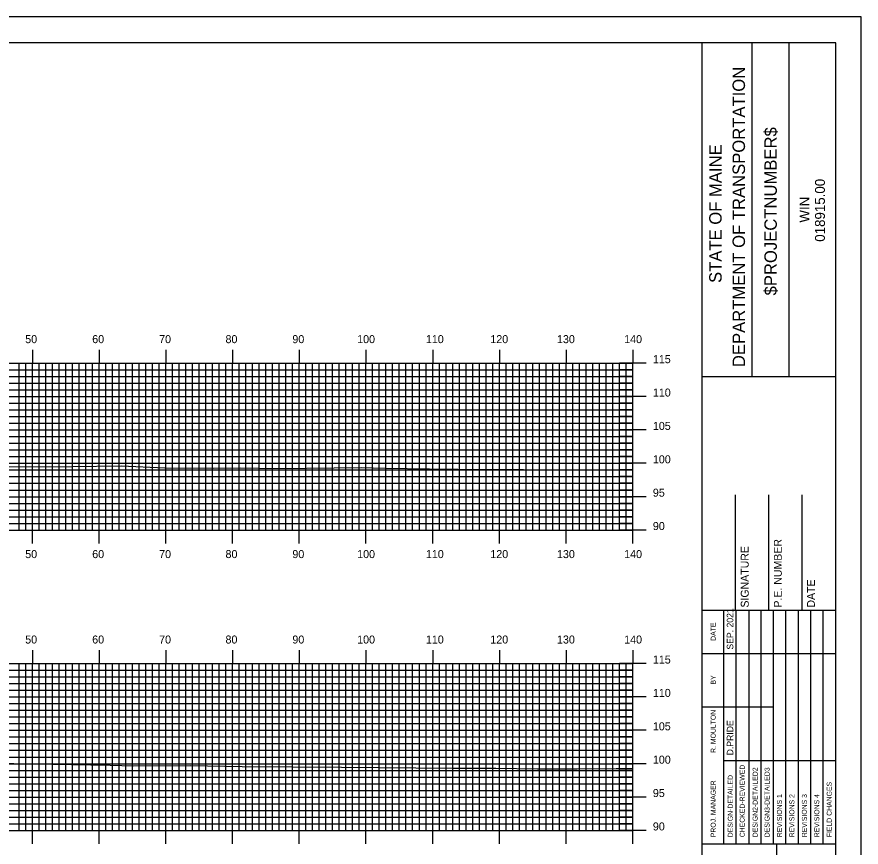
# Model space of a CAD drawing. Extents: x 1773990 to 1774333, y 442591 to 442811.
# Drawn here: x 1774203.3 to 1774329.9, y 442686.2 to 442810.5 of the extents above; entities that cross this region are included whole.
import ezdxf

# ---------------------------------------------------------------- set-up
doc = ezdxf.new("R2010")
doc.units = 0
for name, color, linetype in [('BORDER', 7, 'Continuous'), ('H_V ANNOTATION', 7, 'Continuous'), ('MAJOR', 7, 'Continuous'), ('MINOR', 7, 'Continuous'), ('PLOT BOUNDARY', 7, 'Continuous'), ('S_Roadway_Centerline', 7, 'Continuous')]:
    doc.layers.add(name, color=color, linetype=linetype)

msp = doc.modelspace()

# ---------------------------------------------------------------- linework, layer by layer
at = {"layer": 'BORDER'}
for p, q in [((1774306.06, 442596.67), (1774306.06, 442806.67)), ((1774313.52, 442756.66), (1774313.52, 442806.66)), ((1774319.11, 442756.66), (1774319.11, 442806.66)), ((1774306.06, 442756.65), (1774326.06, 442756.65)), ((1774311.06, 442721.67), (1774311.06, 442738.97)), ((1774316.06, 442721.67), (1774316.06, 442738.97)), ((1774321.06, 442721.67), (1774321.06, 442738.97)), ((1774306.06, 442721.67), (1774326.06, 442721.67)), ((1774306.06, 442686.67), (1774326.06, 442686.67)), ((1774317.24, 442616.67), (1774317.24, 442686.67))]:
    msp.add_line(p, q, dxfattribs=at)
msp.add_lwpolyline([(1774006.06, 442596.67), (1774326.06, 442596.67), (1774326.06, 442806.67), (1774006.06, 442806.67)], close=True, dxfattribs=at)
for points in [[(1774309.29, 442715.17), (1774309.29, 442721.67)], [(1774311.15, 442686.68), (1774311.15, 442721.67)], [(1774313.02, 442721.67), (1774313.02, 442686.68)], [(1774314.88, 442686.68), (1774314.88, 442721.67)], [(1774316.74, 442686.68), (1774316.74, 442721.67)], [(1774318.61, 442686.68), (1774318.61, 442721.67)], [(1774320.47, 442686.68), (1774320.47, 442721.67)], [(1774322.33, 442686.68), (1774322.33, 442721.67)], [(1774324.2, 442686.68), (1774324.2, 442721.67)], [(1774309.29, 442686.68), (1774309.29, 442720.26)], [(1774306.06, 442715.17), (1774326.06, 442715.17)], [(1774306.06, 442707.17), (1774309.29, 442707.17)], [(1774309.29, 442707.17), (1774316.74, 442707.17)], [(1774309.29, 442699.17), (1774326.06, 442699.17)]]:
    msp.add_lwpolyline(points, dxfattribs=at)
at = {"layer": 'MAJOR'}
for p, q in [((1774205.66, 442760.67), (1774205.66, 442758.67)), ((1774215.66, 442760.67), (1774215.66, 442758.67)), ((1774225.66, 442760.67), (1774225.66, 442758.67)), ((1774235.66, 442760.67), (1774235.66, 442758.67)), ((1774245.66, 442760.67), (1774245.66, 442758.67)), ((1774255.66, 442760.67), (1774255.66, 442758.67)), ((1774265.66, 442760.67), (1774265.66, 442758.67)), ((1774275.66, 442760.67), (1774275.66, 442758.67)), ((1774285.66, 442760.67), (1774285.66, 442758.67)), ((1774295.66, 442760.67), (1774295.66, 442758.67)), ((1774015.66, 442758.67), (1774295.66, 442758.67)), ((1774015.66, 442758.67), (1774295.66, 442758.67)), ((1774205.66, 442733.67), (1774205.66, 442758.67)), ((1774215.66, 442733.67), (1774215.66, 442758.67)), ((1774225.66, 442733.67), (1774225.66, 442758.67)), ((1774235.66, 442733.67), (1774235.66, 442758.67)), ((1774245.66, 442733.67), (1774245.66, 442758.67)), ((1774255.66, 442733.67), (1774255.66, 442758.67)), ((1774265.66, 442733.67), (1774265.66, 442758.67)), ((1774275.66, 442733.67), (1774275.66, 442758.67)), ((1774285.66, 442733.67), (1774285.66, 442758.67)), ((1774297.66, 442758.67), (1774293.65, 442758.67)), ((1774295.66, 442733.67), (1774295.66, 442758.67)), ((1774295.66, 442733.67), (1774295.66, 442758.67)), ((1774015.66, 442753.67), (1774295.66, 442753.67)), ((1774297.66, 442753.67), (1774293.65, 442753.67)), ((1774015.66, 442748.67), (1774295.66, 442748.67)), ((1774297.66, 442748.67), (1774293.65, 442748.67)), ((1774015.66, 442743.67), (1774295.66, 442743.67)), ((1774297.66, 442743.67), (1774293.65, 442743.67)), ((1774015.66, 442738.67), (1774295.66, 442738.67)), ((1774297.66, 442738.67), (1774293.65, 442738.67)), ((1774015.66, 442733.67), (1774295.66, 442733.67)), ((1774015.66, 442733.67), (1774295.66, 442733.67)), ((1774205.66, 442731.66), (1774205.66, 442733.67)), ((1774215.66, 442731.66), (1774215.66, 442733.67)), ((1774225.66, 442731.66), (1774225.66, 442733.67)), ((1774235.66, 442731.66), (1774235.66, 442733.67)), ((1774245.66, 442731.66), (1774245.66, 442733.67)), ((1774255.66, 442731.66), (1774255.66, 442733.67)), ((1774265.66, 442731.66), (1774265.66, 442733.67)), ((1774275.66, 442731.66), (1774275.66, 442733.67)), ((1774285.66, 442731.66), (1774285.66, 442733.67)), ((1774297.66, 442733.67), (1774293.65, 442733.67)), ((1774295.66, 442731.66), (1774295.66, 442733.67)), ((1774205.66, 442715.67), (1774205.66, 442713.67)), ((1774215.66, 442715.67), (1774215.66, 442713.67)), ((1774225.66, 442715.67), (1774225.66, 442713.67)), ((1774235.66, 442715.67), (1774235.66, 442713.67)), ((1774245.66, 442715.67), (1774245.66, 442713.67)), ((1774255.66, 442715.67), (1774255.66, 442713.67)), ((1774265.66, 442715.67), (1774265.66, 442713.67)), ((1774275.66, 442715.67), (1774275.66, 442713.67)), ((1774285.66, 442715.67), (1774285.66, 442713.67)), ((1774295.66, 442715.67), (1774295.66, 442713.67)), ((1774015.66, 442713.67), (1774295.66, 442713.67)), ((1774015.66, 442713.67), (1774295.66, 442713.67)), ((1774205.66, 442688.67), (1774205.66, 442713.67)), ((1774215.66, 442688.67), (1774215.66, 442713.67)), ((1774225.66, 442688.67), (1774225.66, 442713.67)), ((1774235.66, 442688.67), (1774235.66, 442713.67)), ((1774245.66, 442688.67), (1774245.66, 442713.67)), ((1774255.66, 442688.67), (1774255.66, 442713.67)), ((1774265.66, 442688.67), (1774265.66, 442713.67)), ((1774275.66, 442688.67), (1774275.66, 442713.67)), ((1774285.66, 442688.67), (1774285.66, 442713.67)), ((1774297.66, 442713.67), (1774293.65, 442713.67)), ((1774295.66, 442688.67), (1774295.66, 442713.67)), ((1774295.66, 442688.67), (1774295.66, 442713.67)), ((1774015.66, 442708.67), (1774295.66, 442708.67)), ((1774297.66, 442708.67), (1774293.65, 442708.67)), ((1774015.66, 442703.67), (1774295.66, 442703.67)), ((1774297.66, 442703.67), (1774293.65, 442703.67)), ((1774015.66, 442698.67), (1774295.66, 442698.67)), ((1774297.66, 442698.67), (1774293.65, 442698.67)), ((1774015.66, 442693.67), (1774295.66, 442693.67)), ((1774297.66, 442693.67), (1774293.65, 442693.67)), ((1774015.66, 442688.67), (1774295.66, 442688.67)), ((1774015.66, 442688.67), (1774295.66, 442688.67)), ((1774205.66, 442686.66), (1774205.66, 442688.67)), ((1774215.66, 442686.66), (1774215.66, 442688.67)), ((1774225.66, 442686.66), (1774225.66, 442688.67)), ((1774235.66, 442686.66), (1774235.66, 442688.67)), ((1774245.66, 442686.66), (1774245.66, 442688.67)), ((1774255.66, 442686.66), (1774255.66, 442688.67)), ((1774265.66, 442686.66), (1774265.66, 442688.67)), ((1774275.66, 442686.66), (1774275.66, 442688.67)), ((1774285.66, 442686.66), (1774285.66, 442688.67)), ((1774297.66, 442688.67), (1774293.65, 442688.67)), ((1774295.66, 442686.66), (1774295.66, 442688.67))]:
    msp.add_line(p, q, dxfattribs=at)
at = {"layer": 'MINOR'}
for p, q in [((1774203.66, 442733.67), (1774203.66, 442758.67)), ((1774204.66, 442733.67), (1774204.66, 442758.67)), ((1774206.66, 442733.67), (1774206.66, 442758.67)), ((1774207.66, 442733.67), (1774207.66, 442758.67)), ((1774208.66, 442733.67), (1774208.66, 442758.67)), ((1774209.66, 442733.67), (1774209.66, 442758.67)), ((1774210.66, 442733.67), (1774210.66, 442758.67)), ((1774211.66, 442733.67), (1774211.66, 442758.67)), ((1774212.66, 442733.67), (1774212.66, 442758.67)), ((1774213.66, 442733.67), (1774213.66, 442758.67)), ((1774214.66, 442733.67), (1774214.66, 442758.67)), ((1774216.66, 442733.67), (1774216.66, 442758.67)), ((1774217.66, 442733.67), (1774217.66, 442758.67)), ((1774218.66, 442733.67), (1774218.66, 442758.67)), ((1774219.66, 442733.67), (1774219.66, 442758.67)), ((1774220.66, 442733.67), (1774220.66, 442758.67)), ((1774221.66, 442733.67), (1774221.66, 442758.67)), ((1774222.66, 442733.67), (1774222.66, 442758.67)), ((1774223.66, 442733.67), (1774223.66, 442758.67)), ((1774224.66, 442733.67), (1774224.66, 442758.67)), ((1774226.66, 442733.67), (1774226.66, 442758.67)), ((1774227.66, 442733.67), (1774227.66, 442758.67)), ((1774228.66, 442733.67), (1774228.66, 442758.67)), ((1774229.66, 442733.67), (1774229.66, 442758.67)), ((1774230.66, 442733.67), (1774230.66, 442758.67)), ((1774231.66, 442733.67), (1774231.66, 442758.67)), ((1774232.66, 442733.67), (1774232.66, 442758.67)), ((1774233.66, 442733.67), (1774233.66, 442758.67)), ((1774234.66, 442733.67), (1774234.66, 442758.67)), ((1774236.66, 442733.67), (1774236.66, 442758.67)), ((1774237.66, 442733.67), (1774237.66, 442758.67)), ((1774238.66, 442733.67), (1774238.66, 442758.67)), ((1774239.66, 442733.67), (1774239.66, 442758.67)), ((1774240.66, 442733.67), (1774240.66, 442758.67)), ((1774241.66, 442733.67), (1774241.66, 442758.67)), ((1774242.66, 442733.67), (1774242.66, 442758.67)), ((1774243.66, 442733.67), (1774243.66, 442758.67)), ((1774244.66, 442733.67), (1774244.66, 442758.67)), ((1774246.66, 442733.67), (1774246.66, 442758.67)), ((1774247.66, 442733.67), (1774247.66, 442758.67)), ((1774248.66, 442733.67), (1774248.66, 442758.67)), ((1774249.66, 442733.67), (1774249.66, 442758.67)), ((1774250.66, 442733.67), (1774250.66, 442758.67)), ((1774251.66, 442733.67), (1774251.66, 442758.67)), ((1774252.66, 442733.67), (1774252.66, 442758.67)), ((1774253.66, 442733.67), (1774253.66, 442758.67)), ((1774254.66, 442733.67), (1774254.66, 442758.67)), ((1774256.66, 442733.67), (1774256.66, 442758.67)), ((1774257.66, 442733.67), (1774257.66, 442758.67)), ((1774258.66, 442733.67), (1774258.66, 442758.67)), ((1774259.66, 442733.67), (1774259.66, 442758.67)), ((1774260.66, 442733.67), (1774260.66, 442758.67)), ((1774261.66, 442733.67), (1774261.66, 442758.67)), ((1774262.66, 442733.67), (1774262.66, 442758.67)), ((1774263.66, 442733.67), (1774263.66, 442758.67)), ((1774264.66, 442733.67), (1774264.66, 442758.67)), ((1774266.66, 442733.67), (1774266.66, 442758.67)), ((1774267.66, 442733.67), (1774267.66, 442758.67)), ((1774268.66, 442733.67), (1774268.66, 442758.67)), ((1774269.66, 442733.67), (1774269.66, 442758.67)), ((1774270.66, 442733.67), (1774270.66, 442758.67)), ((1774271.66, 442733.67), (1774271.66, 442758.67)), ((1774272.66, 442733.67), (1774272.66, 442758.67)), ((1774273.66, 442733.67), (1774273.66, 442758.67)), ((1774274.66, 442733.67), (1774274.66, 442758.67)), ((1774276.66, 442733.67), (1774276.66, 442758.67)), ((1774277.66, 442733.67), (1774277.66, 442758.67)), ((1774278.66, 442733.67), (1774278.66, 442758.67)), ((1774279.66, 442733.67), (1774279.66, 442758.67)), ((1774280.66, 442733.67), (1774280.66, 442758.67)), ((1774281.66, 442733.67), (1774281.66, 442758.67)), ((1774282.66, 442733.67), (1774282.66, 442758.67)), ((1774283.66, 442733.67), (1774283.66, 442758.67)), ((1774284.66, 442733.67), (1774284.66, 442758.67)), ((1774286.66, 442733.67), (1774286.66, 442758.67)), ((1774287.66, 442733.67), (1774287.66, 442758.67)), ((1774288.66, 442733.67), (1774288.66, 442758.67)), ((1774289.66, 442733.67), (1774289.66, 442758.67)), ((1774290.66, 442733.67), (1774290.66, 442758.67)), ((1774291.66, 442733.67), (1774291.66, 442758.67)), ((1774292.66, 442733.67), (1774292.66, 442758.67)), ((1774293.66, 442733.67), (1774293.66, 442758.67)), ((1774294.66, 442733.67), (1774294.66, 442758.67)), ((1774015.66, 442757.67), (1774295.66, 442757.67)), ((1774295.66, 442757.67), (1774293.65, 442757.67)), ((1774015.66, 442756.67), (1774295.66, 442756.67)), ((1774295.66, 442756.67), (1774293.65, 442756.67)), ((1774015.66, 442755.67), (1774295.66, 442755.67)), ((1774015.66, 442754.67), (1774295.66, 442754.67)), ((1774295.66, 442755.67), (1774293.65, 442755.67)), ((1774295.66, 442754.67), (1774293.65, 442754.67)), ((1774015.66, 442752.67), (1774295.66, 442752.67)), ((1774295.66, 442752.67), (1774293.65, 442752.67)), ((1774015.66, 442751.67), (1774295.66, 442751.67)), ((1774295.66, 442751.67), (1774293.65, 442751.67)), ((1774015.66, 442750.67), (1774295.66, 442750.67)), ((1774015.66, 442749.67), (1774295.66, 442749.67)), ((1774295.66, 442750.67), (1774293.65, 442750.67)), ((1774295.66, 442749.67), (1774293.65, 442749.67)), ((1774015.66, 442747.67), (1774295.66, 442747.67)), ((1774295.66, 442747.67), (1774293.65, 442747.67)), ((1774015.66, 442746.67), (1774295.66, 442746.67)), ((1774295.66, 442746.67), (1774293.65, 442746.67)), ((1774015.66, 442745.67), (1774295.66, 442745.67)), ((1774015.66, 442744.67), (1774295.66, 442744.67)), ((1774295.66, 442745.67), (1774293.65, 442745.67)), ((1774295.66, 442744.67), (1774293.65, 442744.67)), ((1774015.66, 442742.67), (1774295.66, 442742.67)), ((1774295.66, 442742.67), (1774293.65, 442742.67)), ((1774015.66, 442741.67), (1774295.66, 442741.67)), ((1774015.66, 442740.67), (1774295.66, 442740.67)), ((1774295.66, 442741.67), (1774293.65, 442741.67)), ((1774295.66, 442740.67), (1774293.65, 442740.67)), ((1774015.66, 442739.67), (1774295.66, 442739.67)), ((1774295.66, 442739.67), (1774293.65, 442739.67)), ((1774015.66, 442737.67), (1774295.66, 442737.67)), ((1774295.66, 442737.67), (1774293.65, 442737.67)), ((1774015.66, 442736.67), (1774295.66, 442736.67)), ((1774015.66, 442735.67), (1774295.66, 442735.67)), ((1774295.66, 442736.67), (1774293.65, 442736.67)), ((1774295.66, 442735.67), (1774293.65, 442735.67)), ((1774015.66, 442734.67), (1774295.66, 442734.67)), ((1774295.66, 442734.67), (1774293.65, 442734.67)), ((1774203.66, 442688.67), (1774203.66, 442713.67)), ((1774204.66, 442688.67), (1774204.66, 442713.67)), ((1774206.66, 442688.67), (1774206.66, 442713.67)), ((1774207.66, 442688.67), (1774207.66, 442713.67)), ((1774208.66, 442688.67), (1774208.66, 442713.67)), ((1774209.66, 442688.67), (1774209.66, 442713.67)), ((1774210.66, 442688.67), (1774210.66, 442713.67)), ((1774211.66, 442688.67), (1774211.66, 442713.67)), ((1774212.66, 442688.67), (1774212.66, 442713.67)), ((1774213.66, 442688.67), (1774213.66, 442713.67)), ((1774214.66, 442688.67), (1774214.66, 442713.67)), ((1774216.66, 442688.67), (1774216.66, 442713.67)), ((1774217.66, 442688.67), (1774217.66, 442713.67)), ((1774218.66, 442688.67), (1774218.66, 442713.67)), ((1774219.66, 442688.67), (1774219.66, 442713.67)), ((1774220.66, 442688.67), (1774220.66, 442713.67)), ((1774221.66, 442688.67), (1774221.66, 442713.67)), ((1774222.66, 442688.67), (1774222.66, 442713.67)), ((1774223.66, 442688.67), (1774223.66, 442713.67)), ((1774224.66, 442688.67), (1774224.66, 442713.67)), ((1774226.66, 442688.67), (1774226.66, 442713.67)), ((1774227.66, 442688.67), (1774227.66, 442713.67)), ((1774228.66, 442688.67), (1774228.66, 442713.67)), ((1774229.66, 442688.67), (1774229.66, 442713.67)), ((1774230.66, 442688.67), (1774230.66, 442713.67)), ((1774231.66, 442688.67), (1774231.66, 442713.67)), ((1774232.66, 442688.67), (1774232.66, 442713.67)), ((1774233.66, 442688.67), (1774233.66, 442713.67)), ((1774234.66, 442688.67), (1774234.66, 442713.67)), ((1774236.66, 442688.67), (1774236.66, 442713.67)), ((1774237.66, 442688.67), (1774237.66, 442713.67)), ((1774238.66, 442688.67), (1774238.66, 442713.67)), ((1774239.66, 442688.67), (1774239.66, 442713.67)), ((1774240.66, 442688.67), (1774240.66, 442713.67)), ((1774241.66, 442688.67), (1774241.66, 442713.67)), ((1774242.66, 442688.67), (1774242.66, 442713.67)), ((1774243.66, 442688.67), (1774243.66, 442713.67)), ((1774244.66, 442688.67), (1774244.66, 442713.67)), ((1774246.66, 442688.67), (1774246.66, 442713.67)), ((1774247.66, 442688.67), (1774247.66, 442713.67)), ((1774248.66, 442688.67), (1774248.66, 442713.67)), ((1774249.66, 442688.67), (1774249.66, 442713.67)), ((1774250.66, 442688.67), (1774250.66, 442713.67)), ((1774251.66, 442688.67), (1774251.66, 442713.67)), ((1774252.66, 442688.67), (1774252.66, 442713.67)), ((1774253.66, 442688.67), (1774253.66, 442713.67)), ((1774254.66, 442688.67), (1774254.66, 442713.67)), ((1774256.66, 442688.67), (1774256.66, 442713.67)), ((1774257.66, 442688.67), (1774257.66, 442713.67)), ((1774258.66, 442688.67), (1774258.66, 442713.67)), ((1774259.66, 442688.67), (1774259.66, 442713.67)), ((1774260.66, 442688.67), (1774260.66, 442713.67)), ((1774261.66, 442688.67), (1774261.66, 442713.67)), ((1774262.66, 442688.67), (1774262.66, 442713.67)), ((1774263.66, 442688.67), (1774263.66, 442713.67)), ((1774264.66, 442688.67), (1774264.66, 442713.67)), ((1774266.66, 442688.67), (1774266.66, 442713.67)), ((1774267.66, 442688.67), (1774267.66, 442713.67)), ((1774268.66, 442688.67), (1774268.66, 442713.67)), ((1774269.66, 442688.67), (1774269.66, 442713.67)), ((1774270.66, 442688.67), (1774270.66, 442713.67)), ((1774271.66, 442688.67), (1774271.66, 442713.67)), ((1774272.66, 442688.67), (1774272.66, 442713.67)), ((1774273.66, 442688.67), (1774273.66, 442713.67)), ((1774274.66, 442688.67), (1774274.66, 442713.67)), ((1774276.66, 442688.67), (1774276.66, 442713.67)), ((1774277.66, 442688.67), (1774277.66, 442713.67)), ((1774278.66, 442688.67), (1774278.66, 442713.67)), ((1774279.66, 442688.67), (1774279.66, 442713.67)), ((1774280.66, 442688.67), (1774280.66, 442713.67)), ((1774281.66, 442688.67), (1774281.66, 442713.67)), ((1774282.66, 442688.67), (1774282.66, 442713.67)), ((1774283.66, 442688.67), (1774283.66, 442713.67)), ((1774284.66, 442688.67), (1774284.66, 442713.67)), ((1774286.66, 442688.67), (1774286.66, 442713.67)), ((1774287.66, 442688.67), (1774287.66, 442713.67)), ((1774288.66, 442688.67), (1774288.66, 442713.67)), ((1774289.66, 442688.67), (1774289.66, 442713.67)), ((1774290.66, 442688.67), (1774290.66, 442713.67)), ((1774291.66, 442688.67), (1774291.66, 442713.67)), ((1774292.66, 442688.67), (1774292.66, 442713.67)), ((1774293.66, 442688.67), (1774293.66, 442713.67)), ((1774294.66, 442688.67), (1774294.66, 442713.67)), ((1774015.66, 442712.67), (1774295.66, 442712.67)), ((1774015.66, 442711.67), (1774295.66, 442711.67)), ((1774295.66, 442712.67), (1774293.65, 442712.67)), ((1774295.66, 442711.67), (1774293.65, 442711.67)), ((1774015.66, 442710.67), (1774295.66, 442710.67)), ((1774295.66, 442710.67), (1774293.65, 442710.67)), ((1774015.66, 442709.67), (1774295.66, 442709.67)), ((1774295.66, 442709.67), (1774293.65, 442709.67)), ((1774015.66, 442707.67), (1774295.66, 442707.67)), ((1774015.66, 442706.67), (1774295.66, 442706.67)), ((1774295.66, 442707.67), (1774293.65, 442707.67)), ((1774295.66, 442706.67), (1774293.65, 442706.67)), ((1774015.66, 442705.67), (1774295.66, 442705.67)), ((1774295.66, 442705.67), (1774293.65, 442705.67)), ((1774015.66, 442704.67), (1774295.66, 442704.67)), ((1774295.66, 442704.67), (1774293.65, 442704.67)), ((1774015.66, 442702.67), (1774295.66, 442702.67)), ((1774015.66, 442701.67), (1774295.66, 442701.67)), ((1774295.66, 442702.67), (1774293.65, 442702.67)), ((1774295.66, 442701.67), (1774293.65, 442701.67)), ((1774015.66, 442700.67), (1774295.66, 442700.67)), ((1774295.66, 442700.67), (1774293.65, 442700.67)), ((1774015.66, 442699.67), (1774295.66, 442699.67)), ((1774295.66, 442699.67), (1774293.65, 442699.67)), ((1774015.66, 442697.67), (1774295.66, 442697.67)), ((1774295.66, 442697.67), (1774293.65, 442697.67)), ((1774015.66, 442696.67), (1774295.66, 442696.67)), ((1774295.66, 442696.67), (1774293.65, 442696.67)), ((1774015.66, 442695.67), (1774295.66, 442695.67)), ((1774295.66, 442695.67), (1774293.65, 442695.67)), ((1774015.66, 442694.67), (1774295.66, 442694.67)), ((1774295.66, 442694.67), (1774293.65, 442694.67)), ((1774015.66, 442692.67), (1774295.66, 442692.67)), ((1774295.66, 442692.67), (1774293.65, 442692.67)), ((1774015.66, 442691.67), (1774295.66, 442691.67)), ((1774295.66, 442691.67), (1774293.65, 442691.67)), ((1774015.66, 442690.67), (1774295.66, 442690.67)), ((1774295.66, 442690.67), (1774293.65, 442690.67)), ((1774015.66, 442689.67), (1774295.66, 442689.67)), ((1774295.66, 442689.67), (1774293.65, 442689.67))]:
    msp.add_line(p, q, dxfattribs=at)
at = {"layer": 'PLOT BOUNDARY'}
msp.add_lwpolyline([(1773989.87, 442590.55), (1774329.87, 442590.55), (1774329.87, 442810.55), (1773989.87, 442810.55)], close=True, dxfattribs=at)
at = {"layer": 'S_Roadway_Centerline'}
for points in [[(1774200.85, 442743.13), (1774211.65, 442743.19), (1774218.98, 442743.28), (1774225.53, 442742.99), (1774232.78, 442742.92), (1774236.83, 442743), (1774242.66, 442742.87), (1774250.88, 442743.01), (1774254.92, 442743.02), (1774258.56, 442742.93), (1774265.19, 442742.82), (1774273.73, 442742.76), (1774277.62, 442742.79), (1774280.95, 442742.71), (1774295.66, 442742.7)], [(1774197.06, 442698.82), (1774217.32, 442698.47), (1774220.83, 442698.34), (1774229.29, 442698.4), (1774237.13, 442698.27), (1774251.98, 442698.14), (1774268.7, 442698.01), (1774275.13, 442698.01), (1774281.39, 442697.92), (1774287.3, 442697.92), (1774293.15, 442697.95), (1774295.66, 442697.97)]]:
    msp.add_lwpolyline(points, dxfattribs=at)

# ---------------------------------------------------------------- texts
at = {"layer": 'BORDER'}
for s, height, p in [('DEPARTMENT OF TRANSPORTATION', 1.8635, (1774312.47, 442758.08)), ('$PROJECTNUMBER$', 1.8635, (1774317.24, 442768.82)), ('STATE OF MAINE', 1.8635, (1774308.97, 442770.69)), ('018915.00', 1.491, (1774324.45, 442776.86)), ('WIN', 1.491, (1774322.13, 442779.73)), ('P.E. NUMBER', 1.1811, (1774317.98, 442722.06)), ('SIGNATURE', 1.181, (1774313.02, 442722.06)), ('DATE', 1.181, (1774322.94, 442722.06)), ('SEP. 2021', 0.969, (1774310.71, 442715.76)), ('DATE', 0.743, (1774308.07, 442717.08)), ('BY', 0.743, (1774308.07, 442710.54)), ('R. MOULTON', 0.745, (1774308.07, 442700.28)), ('D.PRIDE', 0.969, (1774310.71, 442699.92)), ('CHECKED-REVIEWED', 0.7455, (1774312.42, 442687.65)), ('DESIGN2-DETAILED2', 0.7455, (1774314.36, 442687.65)), ('DESIGN3-DETAILED3', 0.7455, (1774316.15, 442687.65)), ('DESIGN-DETAILED', 0.7455, (1774310.63, 442687.65)), ('PROJ. MANAGER', 0.7455, (1774308.07, 442687.65)), ('FIELD CHANGES', 0.7455, (1774325.46, 442687.65)), ('REVISIONS 1', 0.7455, (1774318.01, 442687.65)), ('REVISIONS 2', 0.7455, (1774319.87, 442687.65)), ('REVISIONS 3', 0.7455, (1774321.74, 442687.65)), ('REVISIONS 4', 0.7455, (1774323.6, 442687.65))]:
    msp.add_text(s, height=height, rotation=90, dxfattribs=at).set_placement(p)
at = {"layer": 'H_V ANNOTATION'}
for s, p in [('50', (1774204.59, 442761.67)), ('60', (1774214.63, 442761.67)), ('70', (1774224.66, 442761.67)), ('80', (1774234.61, 442761.67)), ('90', (1774244.63, 442761.67)), ('100', (1774254.34, 442761.67)), ('110', (1774264.64, 442761.67)), ('120', (1774274.3, 442761.67)), ('130', (1774284.29, 442761.67)), ('140', (1774294.36, 442761.67)), ('115', (1774298.66, 442758.67)), ('110', (1774298.66, 442753.67)), ('105', (1774298.66, 442748.67)), ('100', (1774298.66, 442743.67)), ('95', (1774298.66, 442738.67)), ('90', (1774298.66, 442733.67)), ('50', (1774204.59, 442729.47)), ('60', (1774214.63, 442729.47)), ('70', (1774224.66, 442729.47)), ('80', (1774234.61, 442729.47)), ('90', (1774244.63, 442729.47)), ('100', (1774254.34, 442729.47)), ('110', (1774264.64, 442729.47)), ('120', (1774274.3, 442729.47)), ('130', (1774284.29, 442729.47)), ('140', (1774294.36, 442729.47)), ('50', (1774204.59, 442716.67)), ('60', (1774214.63, 442716.67)), ('70', (1774224.66, 442716.67)), ('80', (1774234.61, 442716.67)), ('90', (1774244.63, 442716.67)), ('100', (1774254.34, 442716.67)), ('110', (1774264.64, 442716.67)), ('120', (1774274.3, 442716.67)), ('130', (1774284.29, 442716.67)), ('140', (1774294.36, 442716.67)), ('115', (1774298.66, 442713.67)), ('110', (1774298.66, 442708.67)), ('105', (1774298.66, 442703.67)), ('100', (1774298.66, 442698.67)), ('95', (1774298.66, 442693.67)), ('90', (1774298.66, 442688.67))]:
    msp.add_text(s, height=1.2, dxfattribs=at).set_placement(p)

doc.saveas('drawing.dxf')
